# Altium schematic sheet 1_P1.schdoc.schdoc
size 604 x 431 mm; Symbol: Sheet-Symbol_A4; Device: Sheet-Symbol_A4; Company: 嘉立创EDA; Version: V1.0; Page Size: A4; @Project Name: RTL8367S千兆交换机; @Page Count: 1; @Update Date: 2024-06-27; @Create Date: 2024-05-23; @Schematic Name: Schematic1; @Page No: 1; @Page Name: P1
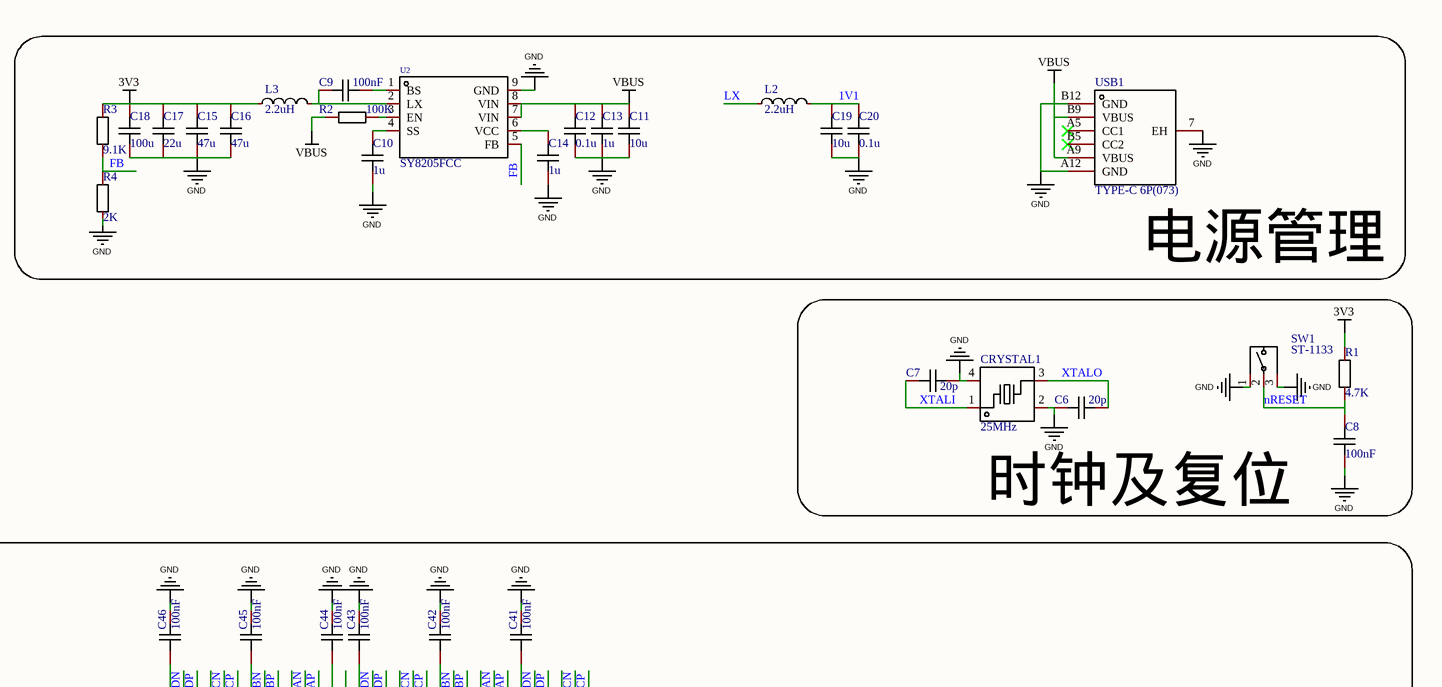
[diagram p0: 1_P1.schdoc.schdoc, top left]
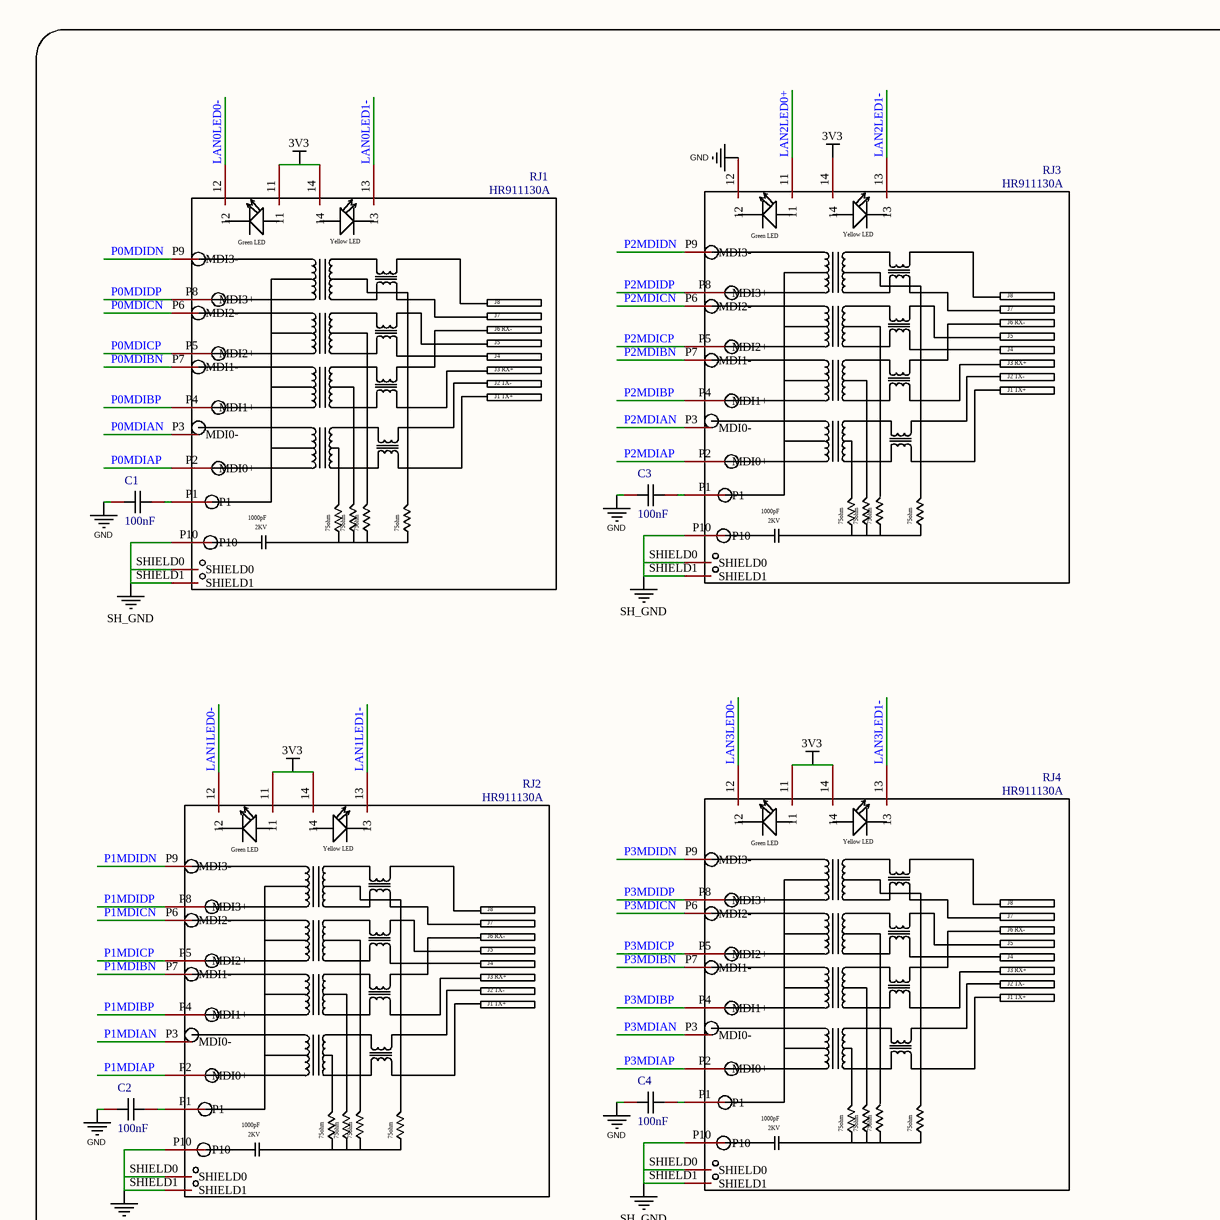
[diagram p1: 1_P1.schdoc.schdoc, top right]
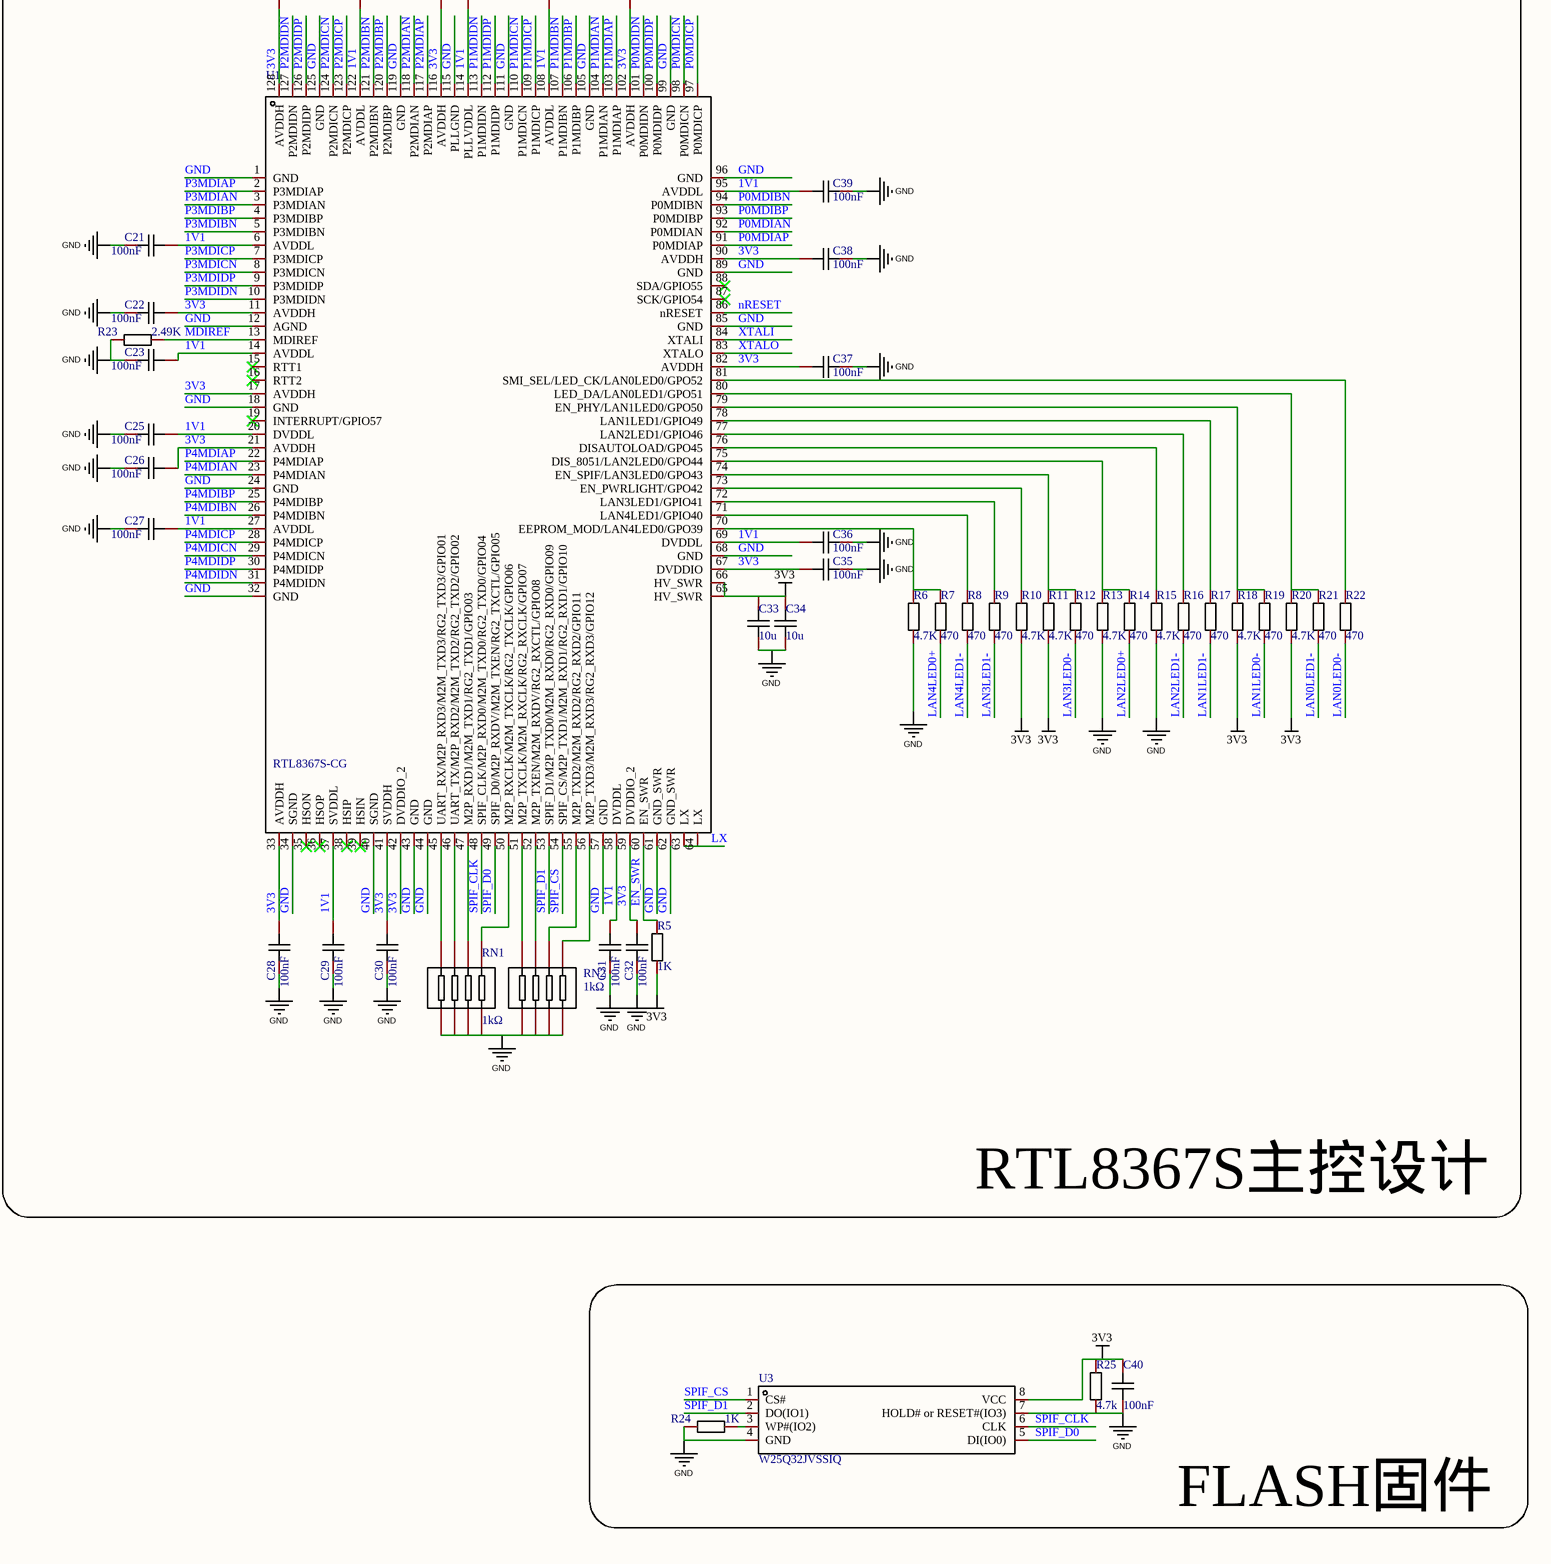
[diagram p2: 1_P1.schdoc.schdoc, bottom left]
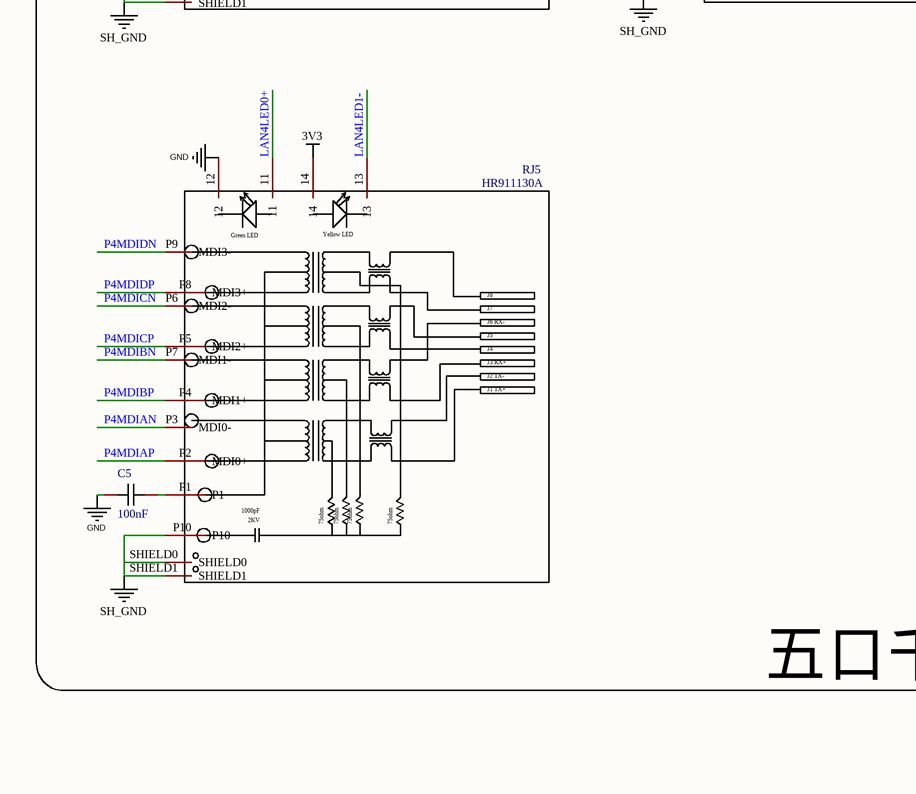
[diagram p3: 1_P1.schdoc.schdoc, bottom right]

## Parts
C1  100nF  [C0603]
C2  100nF  [C0603]
C3  100nF  [C0603]
C4  100nF  [C0603]
C5  100nF  [C0603]
C6  20p  [C0603]
C7  20p  [C0603]
C8  100nF  [C0603]
C9  100nF  [C0603]
C10  1u  [C0603]
C11  10u  [C0603]
C12  0.1u  [C0603]
C13  1u  [C0603]
C14  1u  [C0603]
C15  47u  [C0805]
C16  47u  [C0805]
C17  22u  [C0805]
C18  100u  [C1210]
C19  10u  [C0603]
C20  0.1u  [C0603]
C21  100nF  [C0402]
C22  100nF  [C0402]
C23  100nF  [C0402]
C25  100nF  [C0402]
C26  100nF  [C0402]
C27  100nF  [C0402]
C28  100nF  [C0402]
C29  100nF  [C0402]
C30  100nF  [C0402]
C31  100nF  [C0402]
C32  100nF  [C0402]
C33  10u  [C0603]
C34  10u  [C0603]
C35  100nF  [C0402]
C36  100nF  [C0402]
C37  100nF  [C0402]
C38  100nF  [C0402]
C39  100nF  [C0402]
C40  100nF  [C0402]
C41  100nF  [C0402]
C42  100nF  [C0402]
C43  100nF  [C0402]
C44  100nF  [C0402]
C45  100nF  [C0402]
C46  100nF  [C0402]
CRYSTAL1  25MHz  [CRYSTAL-SMD_4P-L3.2-W2.5-BL]
L2  2.2uH  [IND-SMD_L4.4-W4.2]
L3  2.2uH  [IND-SMD_L4.4-W4.2]
R1  4.7K  [R0603]
R2  100K  [R0603]
R3  9.1K  [R0603]
R4  2K  [R0603]
R5  1K  [R0402]
R6  4.7K  [R0402]
R7  470  [R0402]
R8  470  [R0402]
R9  470  [R0402]
R10  4.7K  [R0402]
R11  4.7K  [R0402]
R12  470  [R0402]
R13  4.7K  [R0402]
R14  470  [R0402]
R15  4.7K  [R0402]
R16  470  [R0402]
R17  470  [R0402]
R18  4.7K  [R0402]
R19  470  [R0402]
R20  4.7K  [R0402]
R21  470  [R0402]
R22  470  [R0402]
R23  2.49K  [R0402]
R24  1K  [R0402]
R25  4.7k  [R0402]
RJ1  HR911130A  [RJ45-TH_HR911130A]
RJ2  HR911130A  [RJ45-TH_HR911130A]
RJ3  HR911130A  [RJ45-TH_HR911130A]
RJ4  HR911130A  [RJ45-TH_HR911130A]
RJ5  HR911130A  [RJ45-TH_HR911130A]
RN1  1kΩ  [RES-ARRAY-SMD_0402-8P-L2.0-W1.0-BL]
RN2  1kΩ  [RES-ARRAY-SMD_0402-8P-L2.0-W1.0-BL]
SW1  ST-1133  [KEY-SMD_ST-1133]
U1  RTL8367S-CG  [LQFP-128_L14.0-W14.0-P0.40-LS16.0-BL]
U2  SY8205FCC  [SOIC-8_L5.0-W4.0-P1.27-LS6.0-BL-EP2.0]
U3  W25Q32JVSSIQ  [SOIC-8_L5.3-W5.3-P1.27-LS8.0-BL]
USB1  TYPE-C 6P(073)  [TYPE-C-SMD_TYPE-C-6P]

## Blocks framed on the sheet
电源管理: C9-C20 L2 L3 R2-R4 U2 USB1
五口千兆网口输出: C1-C5 RJ1-RJ5
时钟及复位: C6-C8 CRYSTAL1 R1 SW1
RTL8367S主控设计: C21-C23 C25-C39 C41-C46 R5-R23 RN1 RN2 U1
FLASH固件: C40 R24 R25 U3

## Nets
3V3: C15.2 C16.2 C17.2 C18.2 C22.1 C26.1 C28.1 C30.1 C32.1 C33.2 C34.2 C35.1 C37.1 C38.1 C40.2 C41.1 C44.1 C46.1 L3.1 R1.2 R3.2 R5.1 R10.1 R11.1 R18.1 R20.1 R25.2 RJ1.11 RJ1.14 RJ2.11 RJ2.14 RJ3.14 RJ4.11 RJ4.14 RJ5.14 U1.11(AVDDH) U1.17(AVDDH) U1.21(AVDDH) U1.33(AVDDH) U1.41(SVDDH) U1.42(DVDDIO_2) U1.59(DVDDIO_2) U1.65(HV_SWR) U1.66(HV_SWR) U1.67(DVDDIO) U1.82(AVDDH) U1.90(AVDDH) U1.102(AVDDH) U1.116(AVDDH) U1.128(AVDDH) U3.8(VCC)
GND: C1.1 C2.1 C3.1 C4.1 C5.1 C6.1 C7.2 C8.1 C10.1 C11.1 C12.1 C13.1 C14.1 C15.1 C16.1 C17.1 C18.1 C19.1 C20.1 C21.2 C22.2 C23.2 C25.2 C26.2 C27.2 C28.2 C29.2 C30.2 C31.2 C32.2 C33.1 C34.1 C35.2 C36.2 C37.2 C38.2 C39.2 C40.1 C41.2 C42.2 C43.2 C44.2 C45.2 C46.2 CRYSTAL1.2(GND) CRYSTAL1.4(GND) R4.1 R6.1 R13.1 R15.1 R23.1 R24.1 R25.1 RJ3.12 RJ5.12 RN1.5 RN1.6 RN1.7 RN1.8 RN2.5 RN2.6 RN2.7 RN2.8 SW1.1 SW1.3 U1.1(GND) U1.12(AGND) U1.18(GND) U1.24(GND) U1.32(GND) U1.34(SGND) U1.40(SGND) U1.43(GND) U1.44(GND) U1.57(GND) U1.61(GND_SWR) U1.62(GND_SWR) U1.68(GND) U1.85(GND) U1.89(GND) U1.96(GND) U1.99(GND) U1.105(GND) U1.111(GND) U1.115(PLLGND) U1.119(GND) U1.125(GND) U2.9(GND) U3.4(GND) U3.7(HOLD#_or_RESET#(IO3)) USB1.7(EH) USB1.A12(GND) USB1.B12(GND)
SH_GND: RJ1.P10 RJ1.SHIELD0 RJ1.SHIELD1 RJ2.P10 RJ2.SHIELD0 RJ2.SHIELD1 RJ3.P10 RJ3.SHIELD0 RJ3.SHIELD1 RJ4.P10 RJ4.SHIELD0 RJ4.SHIELD1 RJ5.P10 RJ5.SHIELD0 RJ5.SHIELD1
VBUS: C11.2 C12.2 C13.2 R2.2 U2.7(VIN) U2.8(VIN) USB1.A9(VBUS) USB1.B9(VBUS)
1V1: C19.2 C20.2 C21.1 C23.1 C25.1 C27.1 C29.1 C31.1 C36.1 C39.1 C42.1 C43.1 C45.1 L2.2 U1.6(AVDDL) U1.14(AVDDL) U1.20(DVDDL) U1.27(AVDDL) U1.37(SVDDL) U1.58(DVDDL) U1.69(DVDDL) U1.95(AVDDL) U1.108(AVDDL) U1.114(PLLVDDL) U1.122(AVDDL)
EN_SWR: R5.2 U1.60(EN_SWR)
FB: R3.1 R4.2 U2.5(FB)
LAN0LED0-: R22.1 RJ1.12
LAN0LED1-: R21.1 RJ1.13
LAN1LED0-: R19.1 RJ2.12
LAN1LED1-: R17.1 RJ2.13
LAN2LED0+: R14.1 RJ3.11
LAN2LED1-: R16.1 RJ3.13
LAN3LED0-: R12.1 RJ4.12
LAN3LED1-: R9.1 RJ4.13
LAN4LED0+: R7.1 RJ5.11
LAN4LED1-: R8.1 RJ5.13
LX: L2.1 U1.63(LX) U1.64(LX)
MDIREF: R23.2 U1.13(MDIREF)
nRESET: C8.2 R1.1 SW1.2 U1.86(nRESET)
P0MDIAN: RJ1.P3(MDI0-) U1.92(P0MDIAN)
P0MDIAP: RJ1.P2(MDI0+) U1.91(P0MDIAP)
P0MDIBN: RJ1.P7(MDI1-) U1.94(P0MDIBN)
P0MDIBP: RJ1.P4(MDI1+) U1.93(P0MDIBP)
P0MDICN: RJ1.P6(MDI2-) U1.98(P0MDICN)
P0MDICP: RJ1.P5(MDI2+) U1.97(P0MDICP)
P0MDIDN: RJ1.P9(MDI3-) U1.101(P0MDIDN)
P0MDIDP: RJ1.P8(MDI3+) U1.100(P0MDIDP)
P1MDIAN: RJ2.P3(MDI0-) U1.104(P1MDIAN)
P1MDIAP: RJ2.P2(MDI0+) U1.103(P1MDIAP)
P1MDIBN: RJ2.P7(MDI1-) U1.107(P1MDIBN)
P1MDIBP: RJ2.P4(MDI1+) U1.106(P1MDIBP)
P1MDICN: RJ2.P6(MDI2-) U1.110(P1MDICN)
P1MDICP: RJ2.P5(MDI2+) U1.109(P1MDICP)
P1MDIDN: RJ2.P9(MDI3-) U1.113(P1MDIDN)
P1MDIDP: RJ2.P8(MDI3+) U1.112(P1MDIDP)
P2MDIAN: RJ3.P3(MDI0-) U1.118(P2MDIAN)
P2MDIAP: RJ3.P2(MDI0+) U1.117(P2MDIAP)
P2MDIBN: RJ3.P7(MDI1-) U1.121(P2MDIBN)
P2MDIBP: RJ3.P4(MDI1+) U1.120(P2MDIBP)
P2MDICN: RJ3.P6(MDI2-) U1.124(P2MDICN)
P2MDICP: RJ3.P5(MDI2+) U1.123(P2MDICP)
P2MDIDN: RJ3.P9(MDI3-) U1.127(P2MDIDN)
P2MDIDP: RJ3.P8(MDI3+) U1.126(P2MDIDP)
P3MDIAN: RJ4.P3(MDI0-) U1.3(P3MDIAN)
P3MDIAP: RJ4.P2(MDI0+) U1.2(P3MDIAP)
P3MDIBN: RJ4.P7(MDI1-) U1.5(P3MDIBN)
P3MDIBP: RJ4.P4(MDI1+) U1.4(P3MDIBP)
P3MDICN: RJ4.P6(MDI2-) U1.8(P3MDICN)
P3MDICP: RJ4.P5(MDI2+) U1.7(P3MDICP)
P3MDIDN: RJ4.P9(MDI3-) U1.10(P3MDIDN)
P3MDIDP: RJ4.P8(MDI3+) U1.9(P3MDIDP)
P4MDIAN: RJ5.P3(MDI0-) U1.23(P4MDIAN)
P4MDIAP: RJ5.P2(MDI0+) U1.22(P4MDIAP)
P4MDIBN: RJ5.P7(MDI1-) U1.26(P4MDIBN)
P4MDIBP: RJ5.P4(MDI1+) U1.25(P4MDIBP)
P4MDICN: RJ5.P6(MDI2-) U1.29(P4MDICN)
P4MDICP: RJ5.P5(MDI2+) U1.28(P4MDICP)
P4MDIDN: RJ5.P9(MDI3-) U1.31(P4MDIDN)
P4MDIDP: RJ5.P8(MDI3+) U1.30(P4MDIDP)
SPIF_CLK: U1.48(SPIF_CLK/M2P_RXD0/M2M_TXD0/RG2_TXD0/GPIO04) U3.6(CLK)
SPIF_CS: U1.54(SPIF_CS/M2P_TXD1/M2M_RXD1/RG2_RXD1/GPIO10) U3.1(CS#)
SPIF_D0: U1.49(SPIF_D0/M2P_RXDV/M2M_TXEN/RG2_TXCTL/GPIO05) U3.5(DI(IO0))
SPIF_D1: U1.53(SPIF_D1/M2P_TXD0/M2M_RXD0/RG2_RXD0/GPIO09) U3.2(DO(IO1))
XTALI: C7.1 CRYSTAL1.1 U1.84(XTALI)
XTALO: C6.2 CRYSTAL1.3 U1.83(XTALO)
NetC1_2: C1.2 RJ1.P1
NetC2_2: C2.2 RJ2.P1
NetC3_2: C3.2 RJ3.P1
NetC4_2: C4.2 RJ4.P1
NetC5_2: C5.2 RJ5.P1
NetC9_1: C9.1 L3.2 U2.2(LX)
NetC9_2: C9.2 U2.1(BS)
NetC10_2: C10.2 U2.4(SS)
NetC14_2: C14.2 U2.6(VCC)
NetR2_1: R2.1 U2.3(EN)
NetR6_2: R6.2 R7.2 U1.70(EEPROM_MOD/LAN4LED0/GPO39)
NetR8_2: R8.2 U1.71(LAN4LED1/GPIO40)
NetR9_2: R9.2 U1.72(LAN3LED1/GPIO41)
NetR10_2: R10.2 U1.73(EN_PWRLIGHT/GPO42)
NetR11_2: R11.2 R12.2 U1.74(EN_SPIF/LAN3LED0/GPO43)
NetR13_2: R13.2 R14.2 U1.75(DIS_8051/LAN2LED0/GPO44)
NetR15_2: R15.2 U1.76(DISAUTOLOAD/GPO45)
NetR16_2: R16.2 U1.77(LAN2LED1/GPIO46)
NetR17_2: R17.2 U1.78(LAN1LED1/GPIO49)
NetR18_2: R18.2 R19.2 U1.79(EN_PHY/LAN1LED0/GPO50)
NetR20_2: R20.2 R21.2 U1.80(LED_DA/LAN0LED1/GPO51)
NetR22_2: R22.2 U1.81(SMI_SEL/LED_CK/LAN0LED0/GPO52)
NetR24_2: R24.2 U3.3(WP#(IO2))
NetRN1_1: RN1.1 U1.45(UART_RX/M2P_RXD3/M2M_TXD3/RG2_TXD3/GPIO01)
NetRN1_2: RN1.2 U1.46(UART_TX/M2P_RXD2/M2M_TXD2/RG2_TXD2/GPIO02)
NetRN1_3: RN1.3 U1.47(M2P_RXD1/M2M_TXD1/RG2_TXD1/GPIO03)
NetRN1_4: RN1.4 U1.50(M2P_RXCLK/M2M_TXCLK/RG2_TXCLK/GPIO06)
NetRN2_1: RN2.1 U1.51(M2P_TXCLK/M2M_RXCLK/RG2_RXCLK/GPIO07)
NetRN2_2: RN2.2 U1.52(M2P_TXEN/M2M_RXDV/RG2_RXCTL/GPIO08)
NetRN2_3: RN2.3 U1.55(M2P_TXD2/M2M_RXD2/RG2_RXD2/GPIO11)
NetRN2_4: RN2.4 U1.56(M2P_TXD3/M2M_RXD3/RG2_RXD3/GPIO12)

Not connected (* = marked no-connect by the designer): U1 15(RTT1)* 16(RTT2)* 19(INTERRUPT/GPIO57)* 35(HSON)* 36(HSOP)* 38(HSIP)* 39(HSIN)* 87(SCK/GPIO54)* 88(SDA/GPIO55)*; USB1 A5(CC1)* B5(CC2)*

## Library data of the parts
C1-C14 C19 C20 C33 C34 = CAP_0603: Symbol: CapAcitance; Convert to PCB: yes
C15-C17 = CAP_0805: Symbol: CapAcitance; Convert to PCB: yes
C18 = JMK325ABJ107MM-T: Manufacturer: TAIYO YUDEN(太诱); Add into BOM: yes; Tolerance: ±20%; Voltage Rated: 6.3V; Temperature Coefficient: X5R; Description: 容值:100uF;精度:±20%;额定电压:6.3V;材质(温度系数):X5R;
C21-C23 C25-C32 C35-C46 = CAP_0402: Symbol: CapAcitance; Convert to PCB: yes
CRYSTAL1 = CF4025M00010: Manufacturer: JWT(晶威特); Add into BOM: yes; Crystal Type: 贴片晶振; Normal temperature Frequency Tolerance: ±10ppm; External load capacitor: 10pF; Frequency Stability(Full temperature range): ±20ppm; Description: 晶振类型:贴片晶振;频率:25MHz;常温频差:±10ppm;外接负载电容:10pF;频率稳定度(全温):±20ppm;
L2 L3 = FXL0420-2R2-M: Manufacturer: cjiang(长江微电); Add into BOM: yes; Tolerance: ±20%; Rated Current: 4.5A; Saturation Current (Isat): 5A; DC Resistance (DCR): 58mΩ; Type: 一体成型电感; Description: 电感值:2.2uH;精度:±20%;额定电流:4.5A;饱和电流(Isat):5A;类型:一体成型电感;
R1-R4 = Res_0603: Symbol: 电阻; Convert to PCB: yes
R5-R25 = Res_0402: Symbol: 电阻; Convert to PCB: yes
RJ1-RJ5 = HR911130A: Manufacturer: HANRUN(汉仁); Add into BOM: yes; Connector Type: RJ45插座; Number of Ports: 1; LED: 带LED; Description: 连接器类型:RJ45插座;端口数量:1;屏蔽:-;LED:带LED;等级:-;
RN1 RN2 = EXB28V102JX: Manufacturer: PANASONIC(松下); Symbol: EXB-28V102JX; Add into BOM: yes; Number of Resistors: 4; Tolerance: ±5%; Power(Watts): 63mW; Temperature Coefficient: ±200ppm/℃; Description: 电阻器数:4;阻值:1kΩ;精度:±5%;单个元件功率:63mW;温度系数:±200ppm/℃;
SW1 = ST-1133: Manufacturer: RISHENG(日昇); Add into BOM: yes; Circuit: 单刀单掷; Actuator Style: 圆形按钮; Operating Force: 180gf; Switch Length: 4.5mm; Switch Width: 3.4mm; Contact Current: 50mA; Voltage Rating (DC): 12V; Insulation Resistance: 100MΩ; Actuator/Cap Color: 白色; Pin Style: SMD接片; Mechanical Life: 10万次; Description: 电路结构:单刀单掷;按钮形状:圆形按钮;作用力:180gf;安装方式:卧贴;开关长度:4.5mm;开关宽度:3.4mm;触点电流:50mA;额定电压(DC):12V;绝缘电阻:100MΩ;机械寿命:10万次;
U1 = RTL8367S-CG: Manufacturer: REALTEK(瑞昱); Add into BOM: yes; Description: 应用功能:-;通道数:-;接口类型:-;
U2 = SY8205FCC: Manufacturer: silergy(矽力杰); Add into BOM: yes; Function: 降压型; Switch tube (built-in/external): 内置; Description: 功能类型:降压型;输入电压:-;输出电流(最大值):-;
U3 = W25Q32JVSSIQ: Manufacturer: WINBOND(华邦); Symbol: W25Q32JVSSIQ_C179173; Add into BOM: yes
USB1 = TYPE-C 6P(073): Manufacturer: SHOU HAN(首韩); Add into BOM: yes; Gender: 母; Number of Ports: 1; Current Rating - Power (Max): 5A; Description: 连接器类型:Type-C;标准:-;公母:母;端口数量:1;触点数量:6P;安装方式:卧贴;额定电流 - 电源:5A;工作温度范围:-25℃~+85℃;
